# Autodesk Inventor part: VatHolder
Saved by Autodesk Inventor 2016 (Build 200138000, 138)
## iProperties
Created: 2016-03
Part Number: VatHolder
Material: Generic
Document SubType Name: Modeling
Designer: bongo_000
Density: 1 g/cm^3
Appearance: Default
Author: bongo_000
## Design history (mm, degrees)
feature "SOLID1"
body "Solid1"
